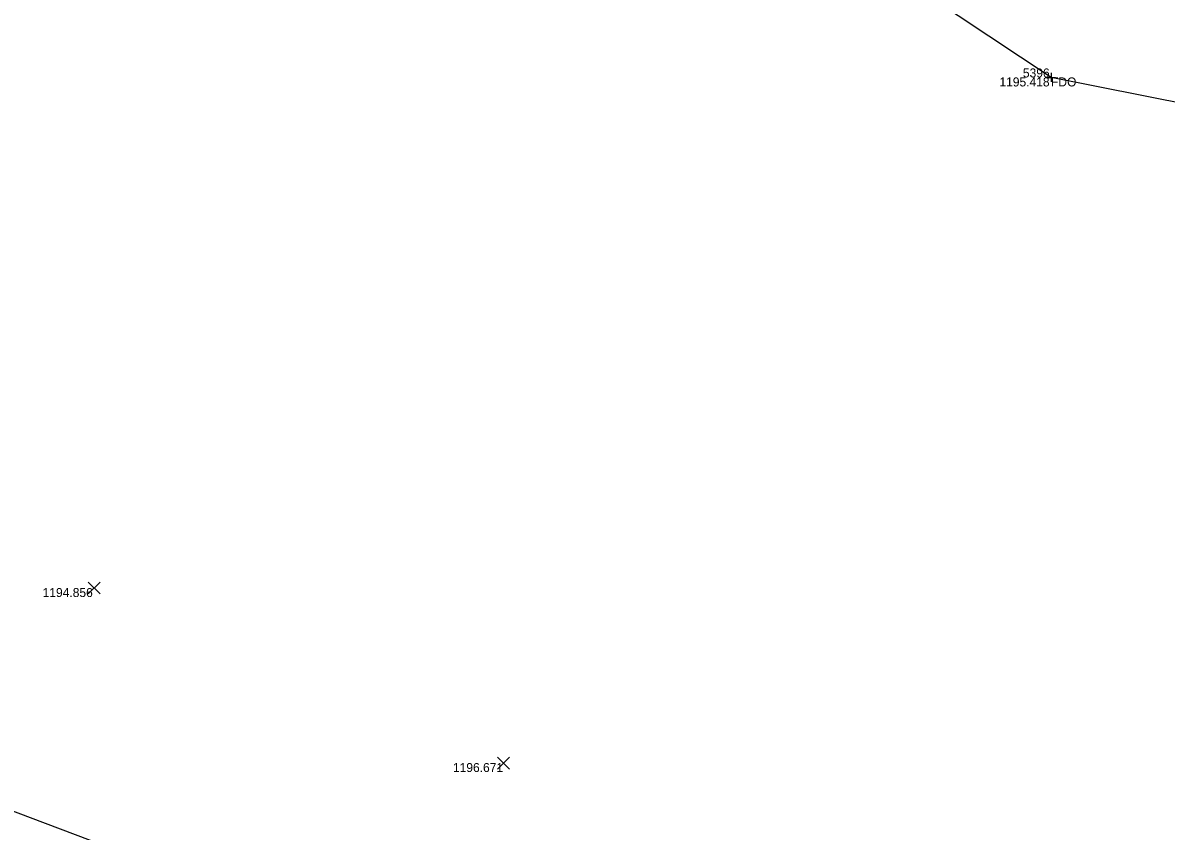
# Model space of a CAD drawing. Extents: x 2044996 to 2050343, y 455232 to 458054.
# Drawn here: x 2047332.3 to 2047459.4, y 457126.5 to 457216.4 of the extents above; entities that cross this region are included whole.
import ezdxf

# ---------------------------------------------------------------- set-up
doc = ezdxf.new("R2010")
doc.units = 0
for name, color, linetype in [('Default', 7, 'Continuous'), ('DR_X_Elev_Flow', 7, 'Continuous'), ('DT_X_Contour_Minor', 7, 'Continuous'), ('DT_X_Contour_Text', 7, 'Continuous'), ('DT_X_Spot_Elev', 7, 'Continuous'), ('DT_X_Triangles', 7, 'Continuous'), ('SV_X_Top_of_Bank', 7, 'Continuous')]:
    doc.layers.add(name, color=color, linetype=linetype)

msp = doc.modelspace()

# ---------------------------------------------------------------- linework, layer by layer
at = {"layer": 'Default'}
msp.add_lwpolyline([(2047593.97, 457240.01), (2047493.12, 457201.08), (2047446.62, 457210.33), (2047381.19, 457253.8), (2047314.69, 457278.12), (2047219.94, 457285.5), (2047164.25, 457287.21), (2047093.51, 457281.46), (2047021.48, 457247.68)], dxfattribs=at)
at = {"layer": 'DR_X_Elev_Flow'}
for p, q in [((2047446.12, 457210.33), (2047447.12, 457210.33)), ((2047446.62, 457210.83), (2047446.62, 457209.83)), ((2047446.62, 457210.33), (2047446.62, 457210.33))]:
    msp.add_line(p, q, dxfattribs=at)
at = {"layer": 'DT_X_Spot_Elev'}
for p, q in [((2047339.57, 457152.86), (2047340.91, 457154.19)), ((2047339.57, 457154.19), (2047340.91, 457152.86)), ((2047385.06, 457133.38), (2047386.4, 457134.71)), ((2047385.06, 457134.71), (2047386.4, 457133.38))]:
    msp.add_line(p, q, dxfattribs=at)
at = {"layer": 'SV_X_Top_of_Bank'}
msp.add_lwpolyline([(2046651.93, 457311.46), (2046700.58, 457305.72), (2046746.85, 457300.37), (2046773.13, 457296.21), (2046810.21, 457291.65), (2046866.31, 457282.87), (2046913.13, 457276.05), (2046946.87, 457270.5), (2046956.84, 457268.66), (2047005.28, 457255.73), (2047019.97, 457251.51), (2047064.03, 457231.46), (2047107.63, 457215.29), (2047146.99, 457200.96), (2047188.63, 457185.75), (2047229.81, 457169.99), (2047277.5, 457150.03), (2047328.36, 457129.78), (2047359.21, 457118.11), (2047442.14, 457085.97), (2047488.03, 457067.35), (2047530.83, 457050.42), (2047563.67, 457038.95)], dxfattribs=at)

# ---------------------------------------------------------------- texts
at = {"layer": 'DT_X_Contour_Minor'}
for s, p in [('1195.418', (2047440.88, 457209.33)), ('1194.856', (2047334.5, 457152.52)), ('1196.671', (2047380.12, 457133.05))]:
    msp.add_text(s, height=1, dxfattribs=at).set_placement(p)
at = {"layer": 'DT_X_Contour_Text'}
msp.add_text('FDO', height=1, dxfattribs=at).set_placement((2047446.62, 457209.33))
at = {"layer": 'DT_X_Triangles'}
msp.add_text('5396', height=1, dxfattribs=at).set_placement((2047443.49, 457210.33))

doc.saveas('drawing.dxf')
